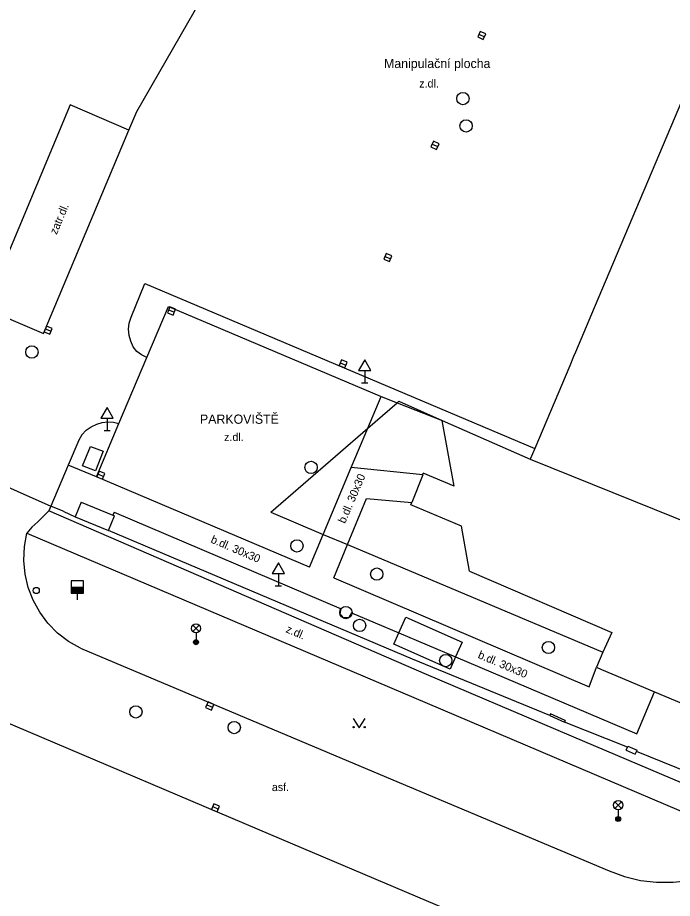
# Model space of a CAD drawing. Extents: x -596024 to -594475, y -1163820 to -1161957.
# Drawn here: x -594807.1 to -594753.9, y -1162363.5 to -1162292 of the extents above; entities that cross this region are included whole.
import ezdxf

# ---------------------------------------------------------------- set-up
doc = ezdxf.new("R2010")
doc.units = 0
for name, color, linetype in [('Level 10', 7, 'Continuous'), ('Level 11', 7, 'Continuous'), ('Level 24', 7, 'Continuous'), ('Level 25', 7, 'Continuous'), ('Level 26', 7, 'Continuous'), ('Level 27', 7, 'Continuous'), ('Level 28', 7, 'Continuous'), ('Level 33', 7, 'Continuous'), ('Level 34', 7, 'Continuous'), ('Level 36', 7, 'Continuous'), ('Level 40', 7, 'Continuous'), ('Level 41', 7, 'Continuous'), ('Level 42', 7, 'Continuous'), ('Level 5', 7, 'Continuous'), ('Level 6', 7, 'Continuous'), ('Level 7', 7, 'Continuous'), ('Level 8', 7, 'Continuous')]:
    doc.layers.add(name, color=color, linetype=linetype)

msp = doc.modelspace()

# ---------------------------------------------------------------- linework, layer by layer
at = {"layer": 'Level 10'}
for points in [[(-594797.39, -1162299.58), (-594790.84, -1162288.2)], [(-594802.78, -1162299.04), (-594809.72, -1162315.57)], [(-594798.03, -1162301.09), (-594802.78, -1162299.04)], [(-594798.03, -1162301.09), (-594797.39, -1162299.58)], [(-594918.11, -1162302.88), (-594889.1, -1162314.85), (-594872.85, -1162321.7), (-594843.94, -1162333.88), (-594828.09, -1162340.65), (-594786.51, -1162358.3), (-594761.24, -1162369.02)], [(-594797.85, -1162316.28), (-594796.74, -1162313.55)], [(-594796.74, -1162313.55), (-594765.06, -1162326.95)], [(-594796.57, -1162319.55), (-594794.81, -1162315.42)], [(-594794.81, -1162315.42), (-594777.53, -1162322.72)], [(-594797.87, -1162318.24), (-594798.01, -1162317.76), (-594798.06, -1162317.26), (-594798, -1162316.76), (-594797.85, -1162316.28)], [(-594796.57, -1162319.55), (-594797.01, -1162319.35), (-594797.38, -1162319.06), (-594797.68, -1162318.68), (-594797.87, -1162318.24)], [(-594778.61, -1162325.29), (-594777.53, -1162322.72)], [(-594801.49, -1162325.47), (-594801.08, -1162325.18), (-594800.62, -1162324.98)], [(-594800.65, -1162329.26), (-594798.83, -1162324.93)], [(-594800.62, -1162324.98), (-594800.18, -1162324.84), (-594799.73, -1162324.79), (-594799.27, -1162324.82), (-594798.83, -1162324.93)], [(-594801.84, -1162325.83), (-594802.1, -1162326.26)], [(-594801.49, -1162325.47), (-594801.84, -1162325.83)], [(-594782.24, -1162333.92), (-594779.96, -1162328.49), (-594778.61, -1162325.29)], [(-594802.1, -1162326.26), (-594802.95, -1162328.29), (-594804.35, -1162331.62), (-594804.52, -1162332.02)], [(-594783.36, -1162336.58), (-594800.65, -1162329.26)], [(-594804.52, -1162332.02), (-594805.42, -1162332.91), (-594805.9, -1162333.33), (-594806.31, -1162333.82)], [(-594801.96, -1162343.17), (-594802.93, -1162342.62), (-594803.81, -1162341.94), (-594804.6, -1162341.14), (-594805.26, -1162340.25), (-594805.8, -1162339.27), (-594806.2, -1162338.23), (-594806.46, -1162337.14), (-594806.56, -1162336.03), (-594806.51, -1162334.92), (-594806.31, -1162333.82)], [(-594783.36, -1162336.58), (-594782.24, -1162333.92)], [(-594801.96, -1162343.17), (-594779.17, -1162352.77), (-594759.02, -1162361.25)], [(-594759.02, -1162361.25), (-594757.77, -1162361.71), (-594756.48, -1162362.02), (-594755.16, -1162362.18), (-594753.83, -1162362.18), (-594752.51, -1162362.04), (-594751.21, -1162361.75), (-594749.95, -1162361.31), (-594749.43, -1162361.06)]]:
    msp.add_lwpolyline(points, dxfattribs=at)
at = {"layer": 'Level 11'}
for points in [[(-594804.96, -1162317.6), (-594798.03, -1162301.09)], [(-594809.72, -1162315.57), (-594804.96, -1162317.6)], [(-594798.83, -1162324.93), (-594796.57, -1162319.55)], [(-594777.53, -1162322.72), (-594776.23, -1162323.23)], [(-594776.23, -1162323.23), (-594772.57, -1162324.66)], [(-594765.42, -1162327.81), (-594743.74, -1162336.57)], [(-594800.65, -1162329.26), (-594802.95, -1162328.29)], [(-594774.16, -1162329.08), (-594779.96, -1162328.49)], [(-594780.27, -1162334.75), (-594778.72, -1162331.02)], [(-594778.72, -1162331.02), (-594775.05, -1162331.34)], [(-594752.07, -1162354.57), (-594762.07, -1162350.31), (-594773.85, -1162345.29), (-594804.52, -1162332.02)], [(-594799.23, -1162332.13), (-594799.33, -1162332.36)], [(-594799.23, -1162332.13), (-594780.77, -1162339.97)], [(-594806.31, -1162333.82), (-594774.887, -1162347.169), (-594749.91, -1162357.78)], [(-594781.39, -1162337.44), (-594780.27, -1162334.75)], [(-594781.39, -1162337.44), (-594760.65, -1162346.31)], [(-594779.94, -1162340.3), (-594780.16, -1162340.66), (-594780.58, -1162340.7), (-594780.86, -1162340.38), (-594780.77, -1162339.97)], [(-594779.94, -1162340.3), (-594776.1, -1162341.93)], [(-594776.1, -1162341.93), (-594771.5, -1162343.88)], [(-594771.5, -1162343.88), (-594756.77, -1162350.12)], [(-594760.65, -1162346.31), (-594760.04, -1162344.72)], [(-594756.77, -1162350.12), (-594755.34, -1162346.7)]]:
    msp.add_lwpolyline(points, dxfattribs=at)
at = {"layer": 'Level 24'}
for points in [[(-594776.1, -1162341.93), (-594775.52, -1162340.64)], [(-594775.52, -1162340.64), (-594770.96, -1162342.68)], [(-594776.51, -1162342.83), (-594776.1, -1162341.93)], [(-594771.94, -1162344.87), (-594776.51, -1162342.83)], [(-594770.96, -1162342.68), (-594771.5, -1162343.88)], [(-594771.5, -1162343.88), (-594771.94, -1162344.87)], [(-594763.78, -1162348.51), (-594763.83, -1162348.63)], [(-594763.83, -1162348.63), (-594762.64, -1162349.17)], [(-594762.59, -1162349.05), (-594763.78, -1162348.51)], [(-594762.59, -1162349.05), (-594762.64, -1162349.17)], [(-594757.63, -1162351.44), (-594757.53, -1162351.21), (-594757.49, -1162351.11)], [(-594757.63, -1162351.44), (-594756.9, -1162351.77)], [(-594757.49, -1162351.11), (-594756.75, -1162351.44)], [(-594756.9, -1162351.77), (-594756.8, -1162351.55), (-594756.75, -1162351.44)]]:
    msp.add_lwpolyline(points, dxfattribs=at)
at = {"layer": 'Level 25'}
for points in [[(-594801.89, -1162331.31), (-594802.38, -1162332.49)], [(-594801.89, -1162331.31), (-594799.33, -1162332.36), (-594799.19, -1162332.42)], [(-594802.38, -1162332.49), (-594799.68, -1162333.6)], [(-594799.68, -1162333.6), (-594799.19, -1162332.42)]]:
    msp.add_lwpolyline(points, dxfattribs=at)
at = {"layer": 'Level 26'}
for points in [[(-594801.78, -1162328.35), (-594801.15, -1162326.78)], [(-594801.15, -1162326.78), (-594800.1, -1162327.16)], [(-594800.1, -1162327.16), (-594800.73, -1162328.75)], [(-594800.73, -1162328.75), (-594801.78, -1162328.35)]]:
    msp.add_lwpolyline(points, dxfattribs=at)
at = {"layer": 'Level 27'}
for p, q in [((-594769.588, -1162293.297), (-594769.132, -1162293.503)), ((-594773.388, -1162302.217), (-594772.932, -1162302.423)), ((-594777.222, -1162311.346), (-594776.758, -1162311.534)), ((-594794.792, -1162315.686), (-594794.328, -1162315.874)), ((-594804.812, -1162317.236), (-594804.348, -1162317.424)), ((-594780.851, -1162319.984), (-594780.389, -1162320.176)), ((-594800.54, -1162329.012), (-594800.08, -1162329.208)), ((-594791.691, -1162347.763), (-594791.229, -1162347.957)), ((-594791.211, -1162356.033), (-594790.749, -1162356.227))]:
    msp.add_line(p, q, dxfattribs=at)
for points in [[(-594769.691, -1162293.524), (-594769.236, -1162293.731), (-594769.029, -1162293.276), (-594769.484, -1162293.069)], [(-594773.491, -1162302.445), (-594773.035, -1162302.651), (-594772.829, -1162302.195), (-594773.285, -1162301.989)], [(-594777.316, -1162311.577), (-594776.853, -1162311.766), (-594776.664, -1162311.303), (-594777.127, -1162311.114)], [(-594794.886, -1162315.917), (-594794.423, -1162316.106), (-594794.234, -1162315.643), (-594794.697, -1162315.454)], [(-594804.906, -1162317.468), (-594804.442, -1162317.656), (-594804.254, -1162317.192), (-594804.718, -1162317.004)], [(-594780.947, -1162320.214), (-594780.486, -1162320.407), (-594780.293, -1162319.946), (-594780.754, -1162319.753)], [(-594800.638, -1162329.242), (-594800.178, -1162329.438), (-594799.982, -1162328.978), (-594800.442, -1162328.782)], [(-594791.787, -1162347.994), (-594791.326, -1162348.187), (-594791.133, -1162347.726), (-594791.594, -1162347.533)], [(-594791.307, -1162356.264), (-594790.846, -1162356.457), (-594790.653, -1162355.996), (-594791.114, -1162355.803)]]:
    msp.add_lwpolyline(points, close=True, dxfattribs=at)
for centre in [(-594770.89, -1162298.53), (-594770.64, -1162300.75), (-594805.9, -1162319.11), (-594783.23, -1162328.48), (-594784.37, -1162334.86), (-594777.89, -1162337.15), (-594780.4, -1162340.27), (-594779.28, -1162341.32), (-594763.95, -1162343.11), (-594772.29, -1162344.17), (-594797.45, -1162348.34), (-594789.47, -1162349.61)]:
    msp.add_circle(centre, 0.5, dxfattribs=at)
at = {"layer": 'Level 28'}
for p, q in [((-594802.72, -1162338.2), (-594801.72, -1162338.2)), ((-594802.72, -1162338.25), (-594801.72, -1162338.25)), ((-594802.72, -1162338.3), (-594801.72, -1162338.3)), ((-594802.72, -1162338.35), (-594801.72, -1162338.35)), ((-594802.72, -1162338.4), (-594801.72, -1162338.4)), ((-594802.72, -1162338.45), (-594801.72, -1162338.45)), ((-594802.72, -1162338.5), (-594801.72, -1162338.5)), ((-594802.72, -1162338.55), (-594801.72, -1162338.55)), ((-594802.72, -1162338.6), (-594801.72, -1162338.6)), ((-594802.72, -1162338.65), (-594801.72, -1162338.65)), ((-594802.22, -1162338.7), (-594802.22, -1162339.23))]:
    msp.add_line(p, q, dxfattribs=at)
msp.add_lwpolyline([(-594802.72, -1162338.7), (-594801.72, -1162338.7), (-594801.72, -1162337.7), (-594802.72, -1162337.7)], close=True, dxfattribs=at)
msp.add_circle((-594805.55, -1162338.48), 0.25, dxfattribs=at)
at = {"layer": 'Level 33'}
for p, q in [((-594792.835, -1162341.82), (-594792.305, -1162341.29)), ((-594792.835, -1162341.29), (-594792.305, -1162341.82)), ((-594792.57, -1162341.93), (-594792.57, -1162342.68)), ((-594758.545, -1162356.18), (-594758.015, -1162355.65)), ((-594758.545, -1162355.65), (-594758.015, -1162356.18)), ((-594758.28, -1162356.29), (-594758.28, -1162357.04))]:
    msp.add_line(p, q, dxfattribs=at)
for centre, radius in [((-594792.57, -1162341.555), 0.375), ((-594792.57, -1162342.68), 0.2), ((-594792.57, -1162342.68), 0.145), ((-594792.57, -1162342.68), 0.0876), ((-594758.28, -1162355.915), 0.375), ((-594758.28, -1162357.04), 0.2), ((-594758.28, -1162357.04), 0.145), ((-594758.28, -1162357.04), 0.0876)]:
    msp.add_circle(centre, radius, dxfattribs=at)
at = {"layer": 'Level 34'}
for p, q in [((-594778.87, -1162320.602), (-594778.87, -1162321.62)), ((-594779.12, -1162321.62), (-594778.62, -1162321.62)), ((-594799.79, -1162324.472), (-594799.79, -1162325.49)), ((-594800.04, -1162325.49), (-594799.54, -1162325.49)), ((-594785.88, -1162337.092), (-594785.88, -1162338.11)), ((-594786.13, -1162338.11), (-594785.63, -1162338.11))]:
    msp.add_line(p, q, dxfattribs=at)
for points in [[(-594779.37, -1162320.602), (-594778.37, -1162320.602), (-594778.87, -1162319.736)], [(-594800.29, -1162324.472), (-594799.29, -1162324.472), (-594799.79, -1162323.606)], [(-594786.38, -1162337.092), (-594785.38, -1162337.092), (-594785.88, -1162336.226)]]:
    msp.add_lwpolyline(points, close=True, dxfattribs=at)
at = {"layer": 'Level 36'}
msp.add_lwpolyline([(-594779.82, -1162348.88), (-594779.32, -1162349.63), (-594778.82, -1162348.88)], dxfattribs=at)
for centre in [(-594779.77, -1162349.58), (-594778.871, -1162349.58)]:
    msp.add_circle(centre, 0.05, dxfattribs=at)
at = {"layer": 'Level 5'}
for points in [[(-594750.01, -1162291.36), (-594760.22, -1162315.51)], [(-594760.22, -1162315.51), (-594761.74, -1162319.11)], [(-594761.74, -1162319.11), (-594761.9, -1162319.48)], [(-594761.9, -1162319.48), (-594762.22, -1162320.23)], [(-594762.22, -1162320.23), (-594765.06, -1162326.95), (-594765.42, -1162327.81)], [(-594778.61, -1162325.29), (-594776.23, -1162323.23)], [(-594776.23, -1162323.23), (-594776.1, -1162323.11)], [(-594776.1, -1162323.11), (-594772.57, -1162324.66)], [(-594772.57, -1162324.66), (-594765.42, -1162327.81)], [(-594771.61, -1162330), (-594772.57, -1162324.66)], [(-594786.49, -1162332.13), (-594778.61, -1162325.29)], [(-594774.16, -1162329.08), (-594775.05, -1162331.34)], [(-594774.16, -1162329.08), (-594774.11, -1162328.95)], [(-594771.61, -1162330), (-594774.11, -1162328.95)], [(-594775.13, -1162331.53), (-594775.05, -1162331.34)], [(-594771.02, -1162333.26), (-594775.13, -1162331.53)], [(-594786.49, -1162332.13), (-594782.24, -1162333.92)], [(-594770.36, -1162336.92), (-594771.02, -1162333.26)], [(-594782.24, -1162333.92), (-594780.27, -1162334.75)], [(-594780.27, -1162334.75), (-594759.53, -1162343.5)], [(-594770.36, -1162336.92), (-594758.81, -1162341.88)], [(-594758.81, -1162341.88), (-594759.53, -1162343.5)], [(-594759.53, -1162343.5), (-594760.04, -1162344.72)], [(-594760.04, -1162344.72), (-594759.64, -1162344.89)], [(-594759.64, -1162344.89), (-594757.95, -1162345.6)], [(-594757.95, -1162345.6), (-594755.34, -1162346.7)], [(-594755.34, -1162346.7), (-594749.13, -1162349.32)]]:
    msp.add_lwpolyline(points, dxfattribs=at)
at = {"layer": 'Level 6'}
for points in [[(-594760.22, -1162315.51), (-594761.74, -1162319.11)], [(-594761.9, -1162319.48), (-594762.22, -1162320.23)], [(-594774.16, -1162329.08), (-594775.05, -1162331.34)], [(-594759.64, -1162344.89), (-594757.95, -1162345.6)]]:
    msp.add_lwpolyline(points, dxfattribs=at)
at = {"layer": 'Level 7'}
for points in [[(-594803.37, -1162332.05), (-594804.35, -1162331.62)], [(-594774.98, -1162344.05), (-594799.68, -1162333.6)], [(-594763.83, -1162348.63), (-594774.98, -1162344.05)], [(-594757.53, -1162351.21), (-594762.64, -1162349.17)], [(-594751.37, -1162353.74), (-594756.8, -1162351.55)]]:
    msp.add_lwpolyline(points, dxfattribs=at)
at = {"layer": 'Level 8'}
for points in [[(-594809.85, -1162329.2), (-594804.35, -1162331.62)], [(-594803.37, -1162332.05), (-594802.38, -1162332.49)]]:
    msp.add_lwpolyline(points, dxfattribs=at)

# ---------------------------------------------------------------- texts
at = {"layer": 'Level 40'}
for s, p in [('z.dl.', (-594774.44, -1162297.63)), ('z.dl.', (-594790.29, -1162326.34)), ('asf.', (-594786.41, -1162354.77))]:
    msp.add_text(s, height=0.65, dxfattribs=at).set_placement(p)
for s, rotation, p in [('zatr.dl.', 67.22999, (-594803.89, -1162309.62)), ('b.dl. 30x30', 66.80606, (-594780.47, -1162333.09)), ('b.dl. 30x30', 336.80606, (-594791.43, -1162334.57)), ('z.dl.', 337, (-594785.33, -1162341.85)), ('b.dl. 30x30', 336.80606, (-594769.73, -1162343.94))]:
    msp.add_text(s, height=0.65, rotation=rotation, dxfattribs=at).set_placement(p)
at = {"layer": 'Level 41'}
msp.add_text('PARKOVIŠTĚ', height=0.75, dxfattribs=at).set_placement((-594792.25, -1162324.94))
at = {"layer": 'Level 42'}
msp.add_text('Manipulační plocha', height=0.75, dxfattribs=at).set_placement((-594777.3, -1162296.05))

doc.saveas('drawing.dxf')
